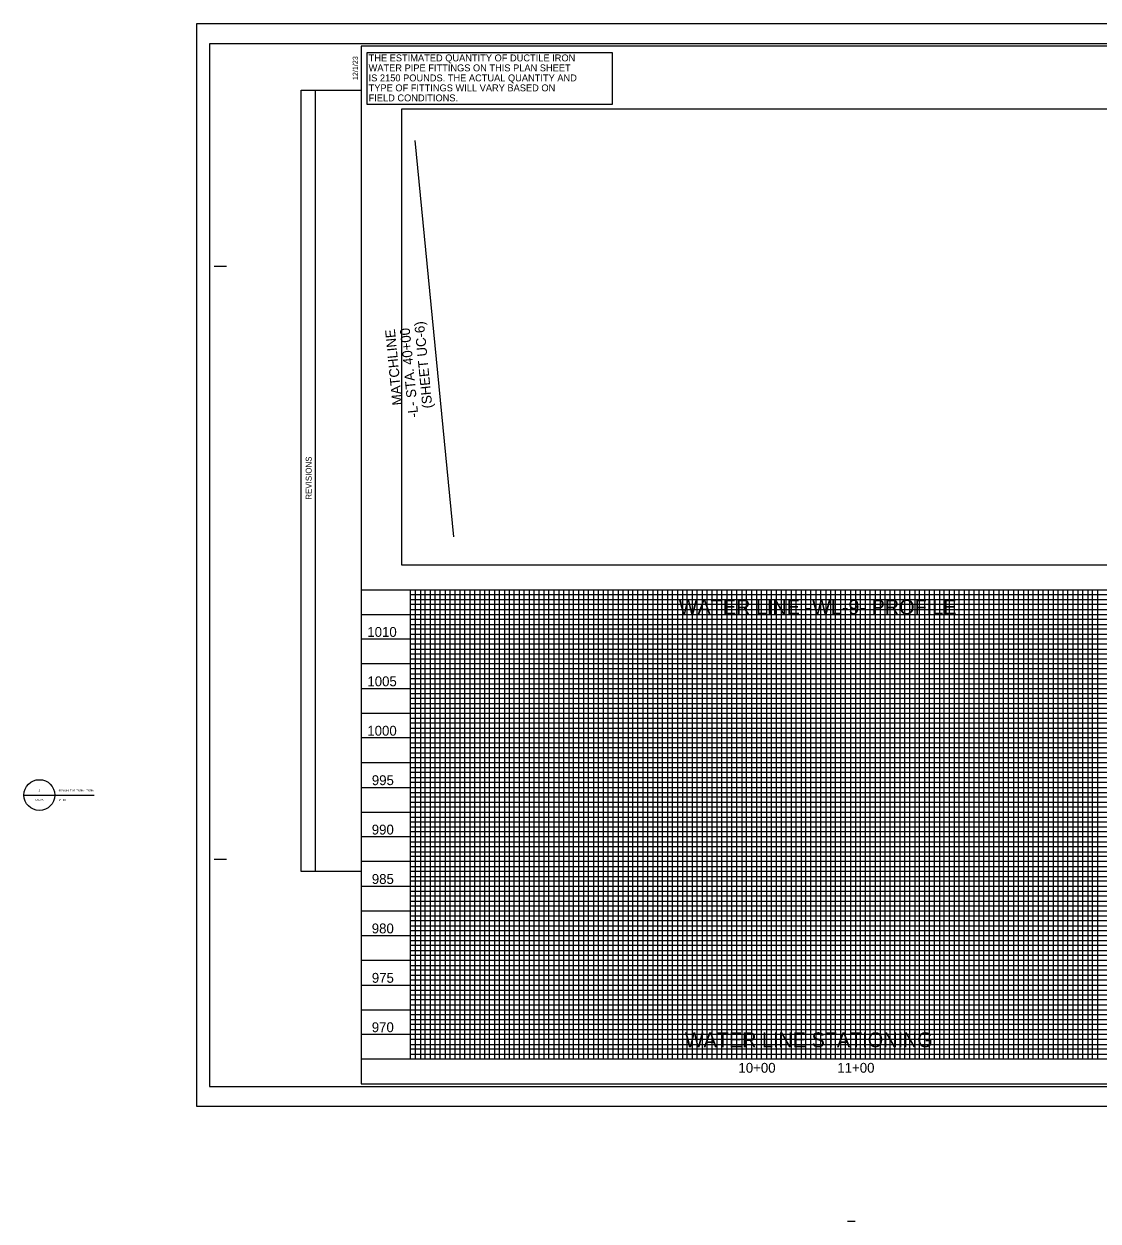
# Model space of a CAD drawing. Extents: x 0 to 4772457, y -312190 to 1506.
# Drawn here: x -0.263 to 1.547, y -0.185 to 1.833 of the extents above; entities that cross this region are included whole.
import ezdxf

# ---------------------------------------------------------------- set-up
doc = ezdxf.new("R2010")
doc.units = 0
for name, color, linetype in [('24 x 36 Plan Sheet CELL', 7, 'Continuous'), ('Default', 7, 'Continuous'), ('Exist Double Yellow Line', 7, 'Continuous'), ('Exist Mini Skip Lane Lines', 7, 'Continuous'), ('Old_Level_38', 7, 'Continuous'), ('Old_Level_57', 7, 'Continuous'), ('Old_Level_63', 7, 'Continuous'), ('Table of Operation CELL', 7, 'Continuous'), ('Timing Chart CELL', 7, 'Continuous')]:
    doc.layers.add(name, color=color, linetype=linetype)

msp = doc.modelspace()

# ---------------------------------------------------------------- linework, layer by layer
at = {"layer": '24 x 36 Plan Sheet CELL'}
msp.add_lwpolyline([(0.315, 1.7851), (0.7284, 1.7851), (0.7284, 1.6977), (0.315, 1.6977)], close=True, dxfattribs=at)
at = {"layer": 'Default'}
msp.add_line((1.125, -0.1854), (1.138, -0.1854), dxfattribs=at)
at = {"layer": 'Exist Double Yellow Line'}
for p, q in [((-0.2634, 0.5329), (-0.2113, 0.5329)), ((-0.2371, 0.5329), (-0.1449, 0.5329))]:
    msp.add_line(p, q, dxfattribs=at)
msp.add_circle((-0.2373, 0.5329), 0.026, dxfattribs=at)
at = {"layer": 'Exist Mini Skip Lane Lines'}
for p, q in [((0.305, 0.8375), (2.5967, 0.8375)), ((2.805, 0.7542), (0.305, 0.7542)), ((0.305, 0.7542), (0.305, 0.6708)), ((0.305, 0.6708), (2.805, 0.6708)), ((2.805, 0.5875), (0.305, 0.5875)), ((0.305, 0.5875), (0.305, 0.5042)), ((0.305, 0.5042), (2.805, 0.5042)), ((2.805, 0.4208), (0.305, 0.4208)), ((0.305, 0.4208), (0.305, 0.3375)), ((0.305, 0.3375), (2.805, 0.3375)), ((2.805, 0.2542), (0.305, 0.2542)), ((0.305, 0.2542), (0.305, 0.1708)), ((0.305, 0.1708), (2.805, 0.1708))]:
    msp.add_line(p, q, dxfattribs=at)
for points in [[(0.43, 0.0875), (0.43, 0.8792), (0.5133, 0.8792), (0.5133, 0.0875)], [(0.5967, 0.0875), (0.5967, 0.8792), (0.68, 0.8792), (0.68, 0.0875)], [(0.7633, 0.0875), (0.7633, 0.8792), (0.8467, 0.8792), (0.8467, 0.0875)], [(0.93, 0.0875), (0.93, 0.8792), (1.0133, 0.8792), (1.0133, 0.0875)], [(1.0967, 0.0875), (1.0967, 0.8792), (1.18, 0.8792), (1.18, 0.0875)], [(1.2633, 0.0875), (1.2633, 0.8792), (1.3467, 0.8792), (1.3467, 0.0875)], [(1.43, 0.0875), (1.43, 0.8792), (1.5133, 0.8792), (1.5133, 0.0875)]]:
    msp.add_lwpolyline(points, dxfattribs=at)
at = {"layer": 'Old_Level_38'}
for points in [[(0.305, 0.8792), (2.5967, 0.8792)], [(0.305, 0.8792), (0.305, 0.0875)], [(0.3883, 0.0875), (0.3883, 0.8792), (0.4717, 0.8792), (0.4717, 0.0875)], [(0.555, 0.0875), (0.555, 0.8792), (0.6383, 0.8792), (0.6383, 0.0875)], [(0.7217, 0.0875), (0.7217, 0.8792), (0.805, 0.8792), (0.805, 0.0875)], [(0.8883, 0.0875), (0.8883, 0.8792), (0.9717, 0.8792), (0.9717, 0.0875)], [(1.055, 0.0875), (1.055, 0.8792), (1.1383, 0.8792), (1.1383, 0.0875)], [(1.2217, 0.0875), (1.2217, 0.8792), (1.305, 0.8792), (1.305, 0.0875)], [(1.3883, 0.0875), (1.3883, 0.8792), (1.4717, 0.8792), (1.4717, 0.0875)], [(2.805, 0.7958), (0.305, 0.7958), (0.305, 0.7125), (2.805, 0.7125)], [(2.805, 0.6292), (0.305, 0.6292), (0.305, 0.5458), (2.805, 0.5458)], [(2.805, 0.4625), (0.305, 0.4625), (0.305, 0.3792), (2.805, 0.3792)], [(2.805, 0.2958), (0.305, 0.2958), (0.305, 0.2125), (2.805, 0.2125)], [(2.805, 0.1292), (0.305, 0.1292)]]:
    msp.add_lwpolyline(points, dxfattribs=at)
at = {"layer": 'Old_Level_57'}
for points in [[(2.5967, 0.8708), (0.3883, 0.8708)], [(0.3967, 0.0875), (0.3967, 0.8792), (0.405, 0.8792), (0.405, 0.0875)], [(0.4133, 0.0875), (0.4133, 0.8792), (0.4217, 0.8792), (0.4217, 0.0875)], [(0.4383, 0.0875), (0.4383, 0.8792), (0.4467, 0.8792), (0.4467, 0.0875)], [(0.455, 0.0875), (0.455, 0.8792), (0.4633, 0.8792), (0.4633, 0.0875)], [(0.48, 0.0875), (0.48, 0.8792), (0.4883, 0.8792), (0.4883, 0.0875)], [(0.4967, 0.0875), (0.4967, 0.8792), (0.505, 0.8792), (0.505, 0.0875)], [(0.5217, 0.0875), (0.5217, 0.8792), (0.53, 0.8792), (0.53, 0.0875)], [(0.5383, 0.0875), (0.5383, 0.8792), (0.5467, 0.8792), (0.5467, 0.0875)], [(0.5633, 0.0875), (0.5633, 0.8792), (0.5717, 0.8792), (0.5717, 0.0875)], [(0.58, 0.0875), (0.58, 0.8792), (0.5883, 0.8792), (0.5883, 0.0875)], [(0.605, 0.0875), (0.605, 0.8792), (0.6133, 0.8792), (0.6133, 0.0875)], [(0.6217, 0.0875), (0.6217, 0.8792), (0.63, 0.8792), (0.63, 0.0875)], [(0.6467, 0.0875), (0.6467, 0.8792), (0.655, 0.8792), (0.655, 0.0875)], [(0.6633, 0.0875), (0.6633, 0.8792), (0.6717, 0.8792), (0.6717, 0.0875)], [(0.6883, 0.0875), (0.6883, 0.8792), (0.6967, 0.8792), (0.6967, 0.0875)], [(0.705, 0.0875), (0.705, 0.8792), (0.7133, 0.8792), (0.7133, 0.0875)], [(0.73, 0.0875), (0.73, 0.8792), (0.7383, 0.8792), (0.7383, 0.0875)], [(0.7467, 0.0875), (0.7467, 0.8792), (0.755, 0.8792), (0.755, 0.0875)], [(0.7717, 0.0875), (0.7717, 0.8792), (0.78, 0.8792), (0.78, 0.0875)], [(0.7883, 0.0875), (0.7883, 0.8792), (0.7967, 0.8792), (0.7967, 0.0875)], [(0.8133, 0.0875), (0.8133, 0.8792), (0.8217, 0.8792), (0.8217, 0.0875)], [(0.83, 0.0875), (0.83, 0.8792), (0.8383, 0.8792), (0.8383, 0.0875)], [(0.855, 0.0875), (0.855, 0.8792), (0.8633, 0.8792), (0.8633, 0.0875)], [(0.8717, 0.0875), (0.8717, 0.8792), (0.88, 0.8792), (0.88, 0.0875)], [(0.8967, 0.0875), (0.8967, 0.8792), (0.905, 0.8792), (0.905, 0.0875)], [(0.9133, 0.0875), (0.9133, 0.8792), (0.9217, 0.8792), (0.9217, 0.0875)], [(0.9383, 0.0875), (0.9383, 0.8792), (0.9467, 0.8792), (0.9467, 0.0875)], [(0.955, 0.0875), (0.955, 0.8792), (0.9633, 0.8792), (0.9633, 0.0875)], [(0.98, 0.0875), (0.98, 0.8792), (0.9883, 0.8792), (0.9883, 0.0875)], [(0.9967, 0.0875), (0.9967, 0.8792), (1.005, 0.8792), (1.005, 0.0875)], [(1.0217, 0.0875), (1.0217, 0.8792), (1.03, 0.8792), (1.03, 0.0875)], [(1.0383, 0.0875), (1.0383, 0.8792), (1.0467, 0.8792), (1.0467, 0.0875)], [(1.0633, 0.0875), (1.0633, 0.8792), (1.0717, 0.8792), (1.0717, 0.0875)], [(1.08, 0.0875), (1.08, 0.8792), (1.0883, 0.8792), (1.0883, 0.0875)], [(1.105, 0.0875), (1.105, 0.8792), (1.1133, 0.8792), (1.1133, 0.0875)], [(1.1217, 0.0875), (1.1217, 0.8792), (1.13, 0.8792), (1.13, 0.0875)], [(1.1467, 0.0875), (1.1467, 0.8792), (1.155, 0.8792), (1.155, 0.0875)], [(1.1633, 0.0875), (1.1633, 0.8792), (1.1717, 0.8792), (1.1717, 0.0875)], [(1.1883, 0.0875), (1.1883, 0.8792), (1.1967, 0.8792), (1.1967, 0.0875)], [(1.205, 0.0875), (1.205, 0.8792), (1.2133, 0.8792), (1.2133, 0.0875)], [(1.23, 0.0875), (1.23, 0.8792), (1.2383, 0.8792), (1.2383, 0.0875)], [(1.2467, 0.0875), (1.2467, 0.8792), (1.255, 0.8792), (1.255, 0.0875)], [(1.2717, 0.0875), (1.2717, 0.8792), (1.28, 0.8792), (1.28, 0.0875)], [(1.2883, 0.0875), (1.2883, 0.8792), (1.2967, 0.8792), (1.2967, 0.0875)], [(1.3133, 0.0875), (1.3133, 0.8792), (1.3217, 0.8792), (1.3217, 0.0875)], [(1.33, 0.0875), (1.33, 0.8792), (1.3383, 0.8792), (1.3383, 0.0875)], [(1.355, 0.0875), (1.355, 0.8792), (1.3633, 0.8792), (1.3633, 0.0875)], [(1.3717, 0.0875), (1.3717, 0.8792), (1.38, 0.8792), (1.38, 0.0875)], [(1.3967, 0.0875), (1.3967, 0.8792), (1.405, 0.8792), (1.405, 0.0875)], [(1.4133, 0.0875), (1.4133, 0.8792), (1.4217, 0.8792), (1.4217, 0.0875)], [(1.4383, 0.0875), (1.4383, 0.8792), (1.4467, 0.8792), (1.4467, 0.0875)], [(1.455, 0.0875), (1.455, 0.8792), (1.4633, 0.8792), (1.4633, 0.0875)], [(1.48, 0.0875), (1.48, 0.8792), (1.4883, 0.8792), (1.4883, 0.0875)], [(1.4967, 0.0875), (1.4967, 0.8792), (1.505, 0.8792), (1.505, 0.0875)], [(1.5217, 0.0875), (1.5217, 0.8792), (1.53, 0.8792), (1.53, 0.0875)], [(1.5383, 0.0875), (1.5383, 0.8792), (1.5467, 0.8792), (1.5467, 0.0875)], [(2.5967, 0.8542), (0.3883, 0.8542), (0.3883, 0.8625), (2.5967, 0.8625)], [(2.5967, 0.8292), (0.3883, 0.8292), (0.3883, 0.8375), (0.3883, 0.8458), (2.5967, 0.8458)], [(2.5967, 0.8125), (0.3883, 0.8125), (0.3883, 0.8208), (2.5967, 0.8208)], [(2.7217, 0.7875), (0.3883, 0.7875), (0.3883, 0.7958), (0.3883, 0.8042), (2.5967, 0.8042)], [(2.7217, 0.7708), (0.3883, 0.7708), (0.3883, 0.7792), (2.7217, 0.7792)], [(2.7217, 0.7458), (0.3883, 0.7458), (0.3883, 0.7542), (0.3883, 0.7625), (2.7217, 0.7625)], [(2.7217, 0.7292), (0.3883, 0.7292), (0.3883, 0.7375), (2.7217, 0.7375)], [(0.3883, 0.7042), (0.3883, 0.7125), (0.3883, 0.7208), (2.7217, 0.7208)], [(2.7217, 0.6958), (0.3883, 0.6958), (0.3883, 0.7042), (2.7217, 0.7042)], [(2.7217, 0.6792), (0.3883, 0.6792), (0.3883, 0.6875), (2.7217, 0.6875)], [(2.7217, 0.6542), (0.3883, 0.6542), (0.3883, 0.6625), (2.7217, 0.6625)], [(2.7217, 0.6375), (0.3883, 0.6375), (0.3883, 0.6458), (2.7217, 0.6458)], [(2.7217, 0.6125), (0.3883, 0.6125), (0.3883, 0.6208), (2.7217, 0.6208)], [(2.7217, 0.5958), (0.3883, 0.5958), (0.3883, 0.6042), (2.7217, 0.6042)], [(2.7217, 0.5708), (0.3883, 0.5708), (0.3883, 0.5792), (2.7217, 0.5792)], [(2.7217, 0.5542), (0.3883, 0.5542), (0.3883, 0.5625), (2.7217, 0.5625)], [(2.7217, 0.5292), (0.3883, 0.5292), (0.3883, 0.5375), (2.7217, 0.5375)], [(2.7217, 0.5125), (0.3883, 0.5125), (0.3883, 0.5208), (2.7217, 0.5208)], [(2.7217, 0.4875), (0.3883, 0.4875), (0.3883, 0.4958), (2.7217, 0.4958)], [(2.7217, 0.4708), (0.3883, 0.4708), (0.3883, 0.4792), (2.7217, 0.4792)], [(2.7217, 0.4458), (0.3883, 0.4458), (0.3883, 0.4542), (2.7217, 0.4542)], [(2.7217, 0.4292), (0.3883, 0.4292), (0.3883, 0.4375), (2.7217, 0.4375)], [(2.7217, 0.4042), (0.3883, 0.4042), (0.3883, 0.4125), (2.7217, 0.4125)], [(2.7217, 0.3875), (0.3883, 0.3875), (0.3883, 0.3958), (2.7217, 0.3958)], [(2.7217, 0.3625), (0.3883, 0.3625), (0.3883, 0.3708), (2.7217, 0.3708)], [(2.7217, 0.3458), (0.3883, 0.3458), (0.3883, 0.3542), (2.7217, 0.3542)], [(2.7217, 0.3208), (0.3883, 0.3208), (0.3883, 0.3292), (2.7217, 0.3292)], [(2.7217, 0.3042), (0.3883, 0.3042), (0.3883, 0.3125), (2.7217, 0.3125)], [(2.7217, 0.2792), (0.3883, 0.2792), (0.3883, 0.2875), (2.7217, 0.2875)], [(2.7217, 0.2625), (0.3883, 0.2625), (0.3883, 0.2708), (2.7217, 0.2708)], [(2.7217, 0.2375), (0.3883, 0.2375), (0.3883, 0.2458), (2.7217, 0.2458)], [(2.7217, 0.2208), (0.3883, 0.2208), (0.3883, 0.2292), (2.7217, 0.2292)], [(0.3883, 0.1958), (0.3883, 0.2042), (2.7217, 0.2042)], [(0.3883, 0.0958), (2.7217, 0.0958), (2.7217, 0.1042), (0.3883, 0.1042), (0.3883, 0.1125), (2.7217, 0.1125), (2.7217, 0.1208), (0.3883, 0.1208), (0.3883, 0.1292), (0.3883, 0.1375), (2.7217, 0.1375), (2.7217, 0.1458), (0.3883, 0.1458), (0.3883, 0.1542), (2.7217, 0.1542), (2.7217, 0.1625), (0.3883, 0.1625), (0.3883, 0.1708), (0.3883, 0.1792), (2.7217, 0.1792), (2.7217, 0.1875), (0.3883, 0.1875), (0.3883, 0.1958), (2.7217, 0.1958)]]:
    msp.add_lwpolyline(points, dxfattribs=at)
at = {"layer": 'Old_Level_63'}
for p, q in [((0.2283, 0.4042), (0.2283, 1.7219)), ((0.3955, 1.6368), (0.461, 0.9683)), ((0.0575, 1.425), (0.0783, 1.425)), ((0.0575, 0.425), (0.0783, 0.425)), ((2.805, 0.0875), (0.305, 0.0875)), ((0.305, 0.0458), (0.305, 0.0458)), ((0.305, 0.0458), (0.305, 0.0458)), ((0.305, 0.0458), (0.305, 0.0458)), ((0.305, 0.0458), (0.305, 0.0458)), ((0.305, 0.0458), (0.305, 0.0458))]:
    msp.add_line(p, q, dxfattribs=at)
for points in [[(0.0275, 0.0083), (2.8333, 0.0083), (2.8333, 1.8333), (0.0275, 1.8333)], [(0.0492, 0.0417), (2.8258, 0.0417), (2.8258, 1.8), (0.0492, 1.8)], [(2.805, 1.7958), (0.305, 1.7958), (0.305, 0.0458), (2.805, 0.0458)], [(0.2041, 0.4042), (0.2041, 1.7219), (0.305, 1.7219), (0.305, 0.4042)], [(0.3883, 0.8792), (2.5967, 0.8792), (2.5967, 0.7958), (2.7217, 0.7958), (2.7217, 0.0875), (0.3883, 0.0875)]]:
    msp.add_lwpolyline(points, close=True, dxfattribs=at)
at = {"layer": 'Timing Chart CELL'}
msp.add_lwpolyline([(0.3735, 0.9205), (0.3735, 1.6899), (2.4667, 1.6899), (2.4667, 1.4997), (2.7575, 1.4997), (2.7575, 0.9205)], close=True, dxfattribs=at)

# ---------------------------------------------------------------- texts
at = {"layer": '24 x 36 Plan Sheet CELL'}
for s, p in [('THE ESTIMATED QUANTITY OF DUCTILE IRON', (0.3177, 1.7702)), ('WATER PIPE FITTINGS ON THIS PLAN SHEET', (0.3177, 1.7534)), ('IS 2150 POUNDS. THE ACTUAL QUANTITY AND', (0.3177, 1.7365)), ('TYPE OF FITTINGS WILL VARY BASED ON', (0.3177, 1.7197)), ('FIELD CONDITIONS.', (0.3177, 1.7028))]:
    msp.add_text(s, height=0.011667, dxfattribs=at).set_placement(p)
at = {"layer": 'Exist Double Yellow Line'}
for s, height, p in [('UC-7A', 0.00328, (-0.244, 0.523)), ('2', 0.00328, (-0.2385, 0.5394)), ('50 Scale Plan Profile - Profile', 0.003281, (-0.2048, 0.5394)), ('1"=50\'', 0.00328, (-0.2048, 0.523))]:
    msp.add_text(s, height=height, dxfattribs=at).set_placement(p)
at = {"layer": 'Old_Level_63'}
for s, height, rotation, p in [('12/1/23', 0.00875, 90, (0.2996, 1.7386)), ('MATCHLINE ', 0.01667, 95.5975, (0.3745, 1.191)), ('-L- STA. 40+00', 0.016667, 95.5975, (0.4017, 1.1703)), ('(SHEET UC-6)', 0.016667, 95.5975, (0.4253, 1.1858)), ('REVISIONS', 0.01, 90, (0.2216, 1.0311))]:
    msp.add_text(s, height=height, rotation=rotation, dxfattribs=at).set_placement(p)
for s, p in [('1010', (0.3155, 0.7997)), ('1005', (0.3156, 0.7164)), ('1000', (0.3155, 0.6331)), ('995', (0.3231, 0.5497)), ('990', (0.323, 0.4664)), ('985', (0.3231, 0.3831)), ('980', (0.323, 0.2997)), ('975', (0.3231, 0.2164)), ('970', (0.323, 0.1331)), ('10+00', (0.9412, 0.0647)), ('11+00', (1.1079, 0.0647))]:
    msp.add_text(s, height=0.01667, dxfattribs=at).set_placement(p)
at = {"layer": 'Table of Operation CELL'}
for s, p in [('WATER LINE -WL-9- PROFILE', (0.8406, 0.8376)), ('WATER LINE STATIONING', (0.8509, 0.1078))]:
    msp.add_text(s, height=0.025, dxfattribs=at).set_placement(p)

doc.saveas('drawing.dxf')
